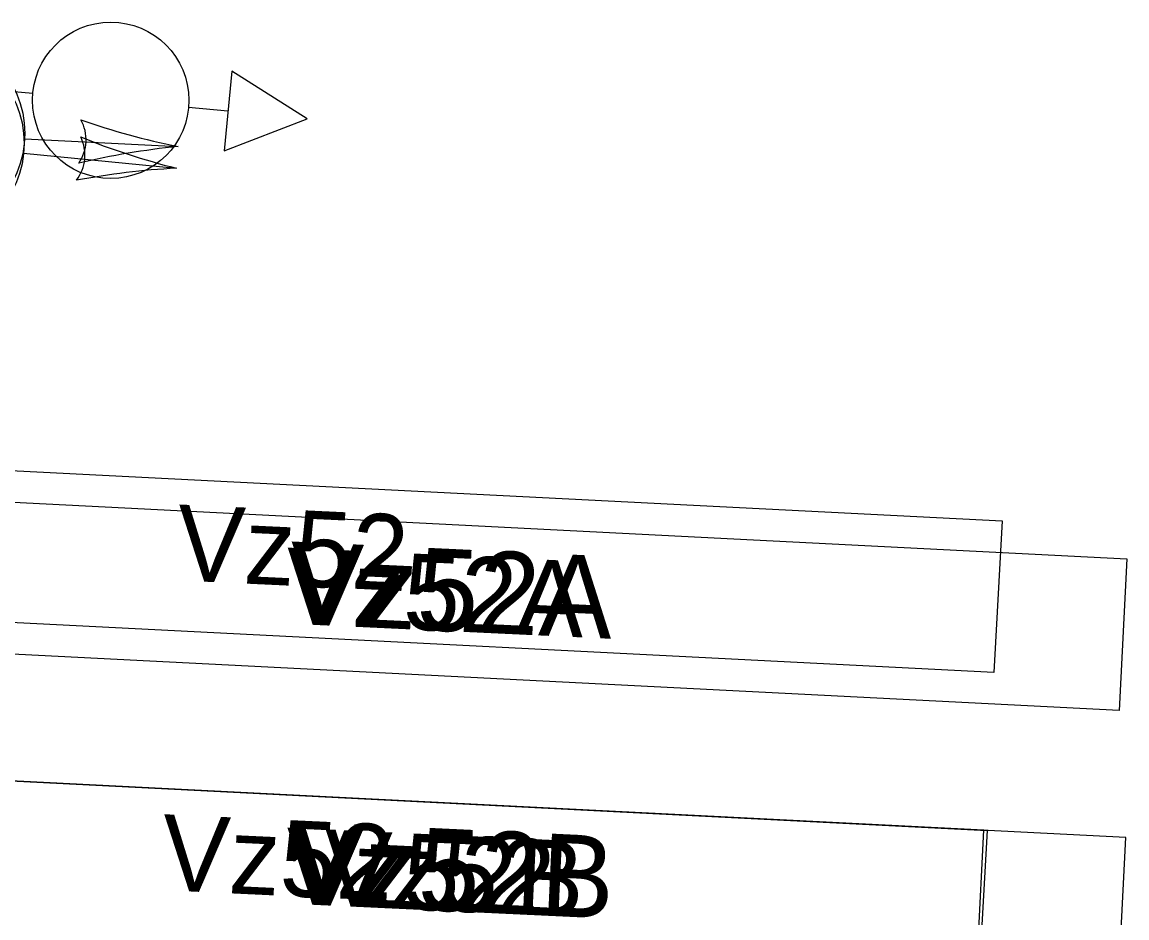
# Model space of a CAD drawing. Extents: x 647787 to 668496, y 640478 to 654412.
# Drawn here: x 659974.72 to 660018.36, y 647427.78 to 647463.17 of the extents above; entities that cross this region are included whole.
import ezdxf

# ---------------------------------------------------------------- set-up
doc = ezdxf.new("R2010")
doc.units = 0
for name, color, linetype in [('TEMP_DETECTION ZONE_Stage 2', 7, 'Continuous'), ('TEMP_DETECTION ZONE_STAGE 3', 7, 'Continuous'), ('TEMP_DETECTION_ZONE_STAGE 5', 7, 'Continuous'), ('TEMP_SIGNAL_HEAD_STAGE 2', 7, 'Continuous'), ('TEMP_SIGNAL_HEAD_STAGE 2 SALEM', 7, 'Continuous'), ('TEMP_SIGNAL_HEAD_Stage 3', 7, 'Continuous'), ('TEMP_SIGNAL_POLES_STAGE 1B', 7, 'Continuous')]:
    doc.layers.add(name, color=color, linetype=linetype)

msp = doc.modelspace()

# ---------------------------------------------------------------- linework, layer by layer
at = {"layer": 'TEMP_DETECTION ZONE_Stage 2'}
for p, q in [((659963.5, 647446.006), (660013.436, 647443.47)), ((660013.436, 647443.47), (660013.099, 647437.479)), ((660013.099, 647437.479), (659963.162, 647440.015))]:
    msp.add_line(p, q, dxfattribs=at)
at = {"layer": 'TEMP_DETECTION ZONE_STAGE 3'}
for p, q in [((659962.906, 647433.77), (660012.842, 647431.235)), ((660012.842, 647431.235), (660012.504, 647425.244))]:
    msp.add_line(p, q, dxfattribs=at)
at = {"layer": 'TEMP_DETECTION_ZONE_STAGE 5'}
for p, q in [((660018.36, 647441.968), (660018.056, 647435.976)), ((660012.705, 647431.241), (659962.769, 647433.777)), ((660018.315, 647430.957), (659968.379, 647433.492)), ((660012.4, 647425.249), (660012.705, 647431.241)), ((660018.01, 647424.964), (660018.315, 647430.957))]:
    msp.add_line(p, q, dxfattribs=at)
for points in [[(659968.424, 647444.504), (660018.36, 647441.968)], [(660018.056, 647435.976), (659968.12, 647438.512)]]:
    msp.add_lwpolyline(points, dxfattribs=at)
at = {"layer": 'TEMP_SIGNAL_HEAD_STAGE 2'}
msp.add_line((659974.824, 647458.562), (659980.881, 647458.252), dxfattribs=at)
msp.add_circle((659970.829, 647458.766), 4, dxfattribs=at)
for centre, radius, start, end in [((659975.621, 647458.52), 1.629, 325.2239, 28.9186), ((659986.77, 647487.127), 29.47, 250.7349, 258.473), ((659983.803, 647428.925), 29.472, 95.6906, 103.4287)]:
    msp.add_arc(centre, radius, start, end, dxfattribs=at)
at = {"layer": 'TEMP_SIGNAL_HEAD_STAGE 2 SALEM'}
msp.add_lwpolyline([(659985.981, 647459.35), (659983.006, 647461.229), (659982.697, 647458.088)], close=True, dxfattribs=at)
msp.add_lwpolyline([(659985.981, 647459.35), (659983.006, 647461.229), (659982.697, 647458.088)], close=True, dxfattribs=at)
for points in [[(659975.145, 647460.348), (659971.697, 647460.648)], [(659975.145, 647460.348), (659971.697, 647460.648)], [(659981.299, 647459.811), (659982.851, 647459.658)], [(659981.299, 647459.811), (659982.851, 647459.658)]]:
    msp.add_lwpolyline(points, dxfattribs=at)
msp.add_circle((659978.222, 647460.079), 3.089, dxfattribs=at)
msp.add_circle((659978.222, 647460.079), 3.089, dxfattribs=at)
at = {"layer": 'TEMP_SIGNAL_HEAD_Stage 3'}
msp.add_line((659974.781, 647457.988), (659980.817, 647457.396), dxfattribs=at)
msp.add_circle((659970.8, 647458.378), 4, dxfattribs=at)
for centre, radius, start, end in [((659975.575, 647457.909), 1.629, 322.5489, 26.2436), ((659988.047, 647485.965), 29.47, 248.0599, 255.798), ((659982.367, 647427.964), 29.472, 93.0156, 100.7537)]:
    msp.add_arc(centre, radius, start, end, dxfattribs=at)
at = {"layer": 'TEMP_SIGNAL_POLES_STAGE 1B'}
for p, q in [((660018.36, 647441.968), (660018.056, 647435.976)), ((660018.315, 647430.957), (659968.379, 647433.492)), ((660018.01, 647424.964), (660018.315, 647430.957))]:
    msp.add_line(p, q, dxfattribs=at)
for points in [[(659968.424, 647444.504), (660018.36, 647441.968)], [(660018.056, 647435.976), (659968.12, 647438.512)]]:
    msp.add_lwpolyline(points, dxfattribs=at)

# ---------------------------------------------------------------- texts
at = {"layer": 'TEMP_DETECTION ZONE_Stage 2'}
msp.add_text('Vz52', height=3, rotation=357.3176, dxfattribs=at).set_placement((659980.773, 647441.117))
at = {"layer": 'TEMP_DETECTION ZONE_STAGE 3'}
msp.add_text('Vz52', height=3, rotation=357.3176, dxfattribs=at).set_placement((659980.179, 647428.881))
at = {"layer": 'TEMP_DETECTION_ZONE_STAGE 5'}
for s, p in [('Vz52A', (659985.057, 647439.413)), ('Vz52B', (659985.043, 647428.354)), ('Vz52', (659986.555, 647428.283))]:
    msp.add_text(s, height=3, rotation=357.3176, dxfattribs=at).set_placement(p)
at = {"layer": 'TEMP_SIGNAL_POLES_STAGE 1B'}
for s, p in [('Vz52A', (659985.198, 647439.406)), ('Vz52B', (659985.249, 647428.344))]:
    msp.add_text(s, height=3.25, rotation=357.3176, dxfattribs=at).set_placement(p)

doc.saveas('drawing.dxf')
